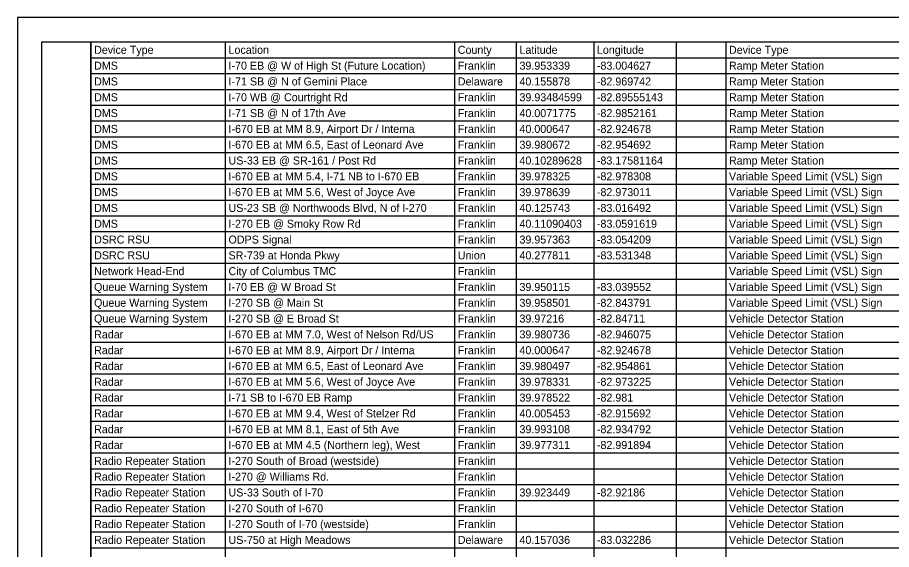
# Model space of a CAD drawing. Extents: x 0 to 34, y 0 to 22.
# Drawn here: x 0 to 17.86, y 11.13 to 22 of the extents above; entities that cross this region are included whole.
import ezdxf

# ---------------------------------------------------------------- set-up
doc = ezdxf.new("R2010")
doc.units = 0
for name, color, linetype in [('SH_Border', 7, 'Continuous'), ('SH_Cut_Line', 7, 'Continuous'), ('SH_Text', 7, 'Continuous')]:
    doc.layers.add(name, color=color, linetype=linetype)

msp = doc.modelspace()

# ---------------------------------------------------------------- linework, layer by layer
at = {"layer": 'SH_Border'}
for points in [[(0.5, 21.5), (1.5, 21.5), (1.5, 0.5), (0.5, 0.5)], [(1.5, 21.5), (33.5, 21.5), (33.5, 0.5), (1.5, 0.5)]]:
    msp.add_lwpolyline(points, close=True, dxfattribs=at)
at = {"layer": 'SH_Cut_Line'}
msp.add_lwpolyline([(0, 0), (34, 0), (34, 22), (0, 22)], close=True, dxfattribs=at)
at = {"layer": 'SH_Text'}
for p, q in [((1.5, 21.5), (27.214, 21.5)), ((1.5, 21.5), (1.5, 0.502)), ((4.246, 21.5), (4.246, 0.502)), ((8.93, 21.5), (8.93, 0.502)), ((10.19, 21.5), (10.19, 0.502)), ((11.773, 21.5), (11.773, 0.502)), ((13.453, 21.5), (13.453, 0.502)), ((14.47, 21.5), (14.47, 0.502)), ((1.5, 21.177), (27.214, 21.177)), ((1.5, 20.854), (27.214, 20.854)), ((1.5, 20.531), (27.214, 20.531)), ((1.5, 20.208), (27.214, 20.208)), ((1.5, 19.885), (27.214, 19.885)), ((1.5, 19.562), (27.214, 19.562)), ((1.5, 19.239), (27.214, 19.239)), ((1.5, 18.916), (27.214, 18.916)), ((1.5, 18.593), (27.214, 18.593)), ((1.5, 18.269), (27.214, 18.269)), ((1.5, 17.946), (27.214, 17.946)), ((1.5, 17.623), (27.214, 17.623)), ((1.5, 17.3), (27.214, 17.3)), ((1.5, 16.977), (27.214, 16.977)), ((1.5, 16.654), (27.214, 16.654)), ((1.5, 16.331), (27.214, 16.331)), ((1.5, 16.008), (27.214, 16.008)), ((1.5, 15.685), (27.214, 15.685)), ((1.5, 15.362), (27.214, 15.362)), ((1.5, 15.039), (27.214, 15.039)), ((1.5, 14.716), (27.214, 14.716)), ((1.5, 14.393), (27.214, 14.393)), ((1.5, 14.07), (27.214, 14.07)), ((1.5, 13.747), (27.214, 13.747)), ((1.5, 13.424), (27.214, 13.424)), ((1.5, 13.101), (27.214, 13.101)), ((1.5, 12.778), (27.214, 12.778)), ((1.5, 12.455), (27.214, 12.455)), ((1.5, 12.132), (27.214, 12.132)), ((1.5, 11.809), (27.214, 11.809)), ((1.5, 11.486), (27.214, 11.486)), ((1.5, 11.162), (27.214, 11.162))]:
    msp.add_line(p, q, dxfattribs=at)

# ---------------------------------------------------------------- texts
for s, height, p in [('Device Type', 0.16346, (1.565, 21.257)), ('Location', 0.1635, (4.311, 21.257)), ('Latitude', 0.1635, (10.255, 21.257)), ('Longitude', 0.1635, (11.837, 21.257)), ('Device Type', 0.16346, (14.535, 21.257)), ('County', 0.1635, (8.995, 21.257)), ('DMS', 0.1635, (1.565, 20.934)), ('I-70 EB @ W of High St (Future Location)', 0.16346, (4.311, 20.934)), ('Franklin', 0.1635, (8.995, 20.934)), ('39.953339', 0.1635, (10.255, 20.934)), ('-83.004627', 0.1635, (11.837, 20.934)), ('Ramp Meter Station', 0.16346, (14.535, 20.934)), ('DMS', 0.1635, (1.565, 20.611)), ('I-71 SB @ N of Gemini Place', 0.16346, (4.311, 20.611)), ('Delaware', 0.1635, (8.995, 20.611)), ('40.155878', 0.1635, (10.255, 20.611)), ('-82.969742', 0.1635, (11.837, 20.611)), ('Ramp Meter Station', 0.16346, (14.535, 20.611)), ('DMS', 0.1635, (1.565, 20.288)), ('I-70 WB @ Courtright Rd', 0.16346, (4.311, 20.288)), ('Franklin', 0.1635, (8.995, 20.288)), ('39.93484599', 0.16346, (10.255, 20.288)), ('-82.89555143', 0.16346, (11.837, 20.288)), ('Ramp Meter Station', 0.16346, (14.535, 20.288)), ('DMS', 0.1635, (1.565, 19.964)), ('I-71 SB @ N of 17th Ave', 0.16346, (4.311, 19.964)), ('Franklin', 0.1635, (8.995, 19.964)), ('40.0071775', 0.1635, (10.255, 19.964)), ('-82.9852161', 0.16346, (11.837, 19.964)), ('Ramp Meter Station', 0.16346, (14.535, 19.964)), ('DMS', 0.1635, (1.565, 19.641)), ('I-670 EB at MM 8.9, Airport Dr / Interna', 0.16346, (4.311, 19.641)), ('Franklin', 0.1635, (8.995, 19.641)), ('40.000647', 0.1635, (10.255, 19.641)), ('-82.924678', 0.1635, (11.837, 19.641)), ('Ramp Meter Station', 0.16346, (14.535, 19.641)), ('DMS', 0.1635, (1.565, 19.318)), ('I-670 EB at MM 6.5, East of Leonard Ave', 0.16346, (4.311, 19.318)), ('Franklin', 0.1635, (8.995, 19.318)), ('39.980672', 0.1635, (10.255, 19.318)), ('-82.954692', 0.1635, (11.837, 19.318)), ('Ramp Meter Station', 0.16346, (14.535, 19.318)), ('DMS', 0.1635, (1.565, 18.995)), ('US-33 EB @ SR-161 / Post Rd', 0.16346, (4.311, 18.995)), ('Franklin', 0.1635, (8.995, 18.995)), ('40.10289628', 0.16346, (10.255, 18.995)), ('-83.17581164', 0.16346, (11.837, 18.995)), ('Ramp Meter Station', 0.16346, (14.535, 18.995)), ('DMS', 0.1635, (1.565, 18.672)), ('I-670 EB at MM 5.4, I-71 NB to I-670 EB', 0.16346, (4.311, 18.672)), ('Franklin', 0.1635, (8.995, 18.672)), ('39.978325', 0.1635, (10.255, 18.672)), ('-82.978308', 0.1635, (11.837, 18.672)), ('Variable Speed Limit (VSL) Sign', 0.16346, (14.535, 18.672)), ('DMS', 0.1635, (1.565, 18.349)), ('I-670 EB at MM 5.6, West of Joyce Ave', 0.16346, (4.311, 18.349)), ('Franklin', 0.1635, (8.995, 18.349)), ('39.978639', 0.1635, (10.255, 18.349)), ('-82.973011', 0.1635, (11.837, 18.349)), ('Variable Speed Limit (VSL) Sign', 0.16346, (14.535, 18.349)), ('DMS', 0.1635, (1.565, 18.026)), ('US-23 SB @ Northwoods Blvd, N of I-270', 0.16346, (4.311, 18.026)), ('Franklin', 0.1635, (8.995, 18.026)), ('40.125743', 0.1635, (10.255, 18.026)), ('-83.016492', 0.1635, (11.837, 18.026)), ('Variable Speed Limit (VSL) Sign', 0.16346, (14.535, 18.026)), ('DMS', 0.1635, (1.565, 17.703)), ('I-270 EB @ Smoky Row Rd', 0.16346, (4.311, 17.703)), ('Franklin', 0.1635, (8.995, 17.703)), ('40.11090403', 0.16346, (10.255, 17.703)), ('-83.0591619', 0.16346, (11.837, 17.703)), ('Variable Speed Limit (VSL) Sign', 0.16346, (14.535, 17.703)), ('DSRC RSU', 0.1635, (1.565, 17.38)), ('ODPS Signal', 0.16346, (4.311, 17.38)), ('Franklin', 0.1635, (8.995, 17.38)), ('39.957363', 0.1635, (10.255, 17.38)), ('-83.054209', 0.1635, (11.837, 17.38)), ('Variable Speed Limit (VSL) Sign', 0.16346, (14.535, 17.38)), ('DSRC RSU', 0.1635, (1.565, 17.057)), ('SR-739 at Honda Pkwy', 0.16346, (4.311, 17.057)), ('Union', 0.1635, (8.995, 17.057)), ('40.277811', 0.1635, (10.255, 17.057)), ('-83.531348', 0.1635, (11.837, 17.057)), ('Variable Speed Limit (VSL) Sign', 0.16346, (14.535, 17.057)), ('Network Head-End', 0.16346, (1.565, 16.734)), ('City of Columbus TMC', 0.16346, (4.311, 16.734)), ('Franklin', 0.1635, (8.995, 16.734)), ('Variable Speed Limit (VSL) Sign', 0.16346, (14.535, 16.734)), ('Queue Warning System', 0.16346, (1.565, 16.411)), ('I-70 EB @ W Broad St', 0.16346, (4.311, 16.411)), ('Franklin', 0.1635, (8.995, 16.411)), ('39.950115', 0.1635, (10.255, 16.411)), ('-83.039552', 0.1635, (11.837, 16.411)), ('Variable Speed Limit (VSL) Sign', 0.16346, (14.535, 16.411)), ('Queue Warning System', 0.16346, (1.565, 16.088)), ('I-270 SB @ Main St', 0.16346, (4.311, 16.088)), ('Franklin', 0.1635, (8.995, 16.088)), ('39.958501', 0.1635, (10.255, 16.088)), ('-82.843791', 0.1635, (11.837, 16.088)), ('Variable Speed Limit (VSL) Sign', 0.16346, (14.535, 16.088)), ('Queue Warning System', 0.16346, (1.565, 15.765)), ('I-270 SB @ E Broad St', 0.16346, (4.311, 15.765)), ('Franklin', 0.1635, (8.995, 15.765)), ('39.97216', 0.1635, (10.255, 15.765)), ('-82.84711', 0.1635, (11.837, 15.765)), ('Vehicle Detector Station', 0.16346, (14.535, 15.765)), ('Radar', 0.1635, (1.565, 15.442)), ('I-670 EB at MM 7.0, West of Nelson Rd/US', 0.16346, (4.311, 15.442)), ('Franklin', 0.1635, (8.995, 15.442)), ('39.980736', 0.1635, (10.255, 15.442)), ('-82.946075', 0.1635, (11.837, 15.442)), ('Vehicle Detector Station', 0.16346, (14.535, 15.442)), ('Radar', 0.1635, (1.565, 15.119)), ('I-670 EB at MM 8.9, Airport Dr / Interna', 0.16346, (4.311, 15.119)), ('Franklin', 0.1635, (8.995, 15.119)), ('40.000647', 0.1635, (10.255, 15.119)), ('-82.924678', 0.1635, (11.837, 15.119)), ('Vehicle Detector Station', 0.16346, (14.535, 15.119)), ('Radar', 0.1635, (1.565, 14.796)), ('I-670 EB at MM 6.5, East of Leonard Ave', 0.16346, (4.311, 14.796)), ('Franklin', 0.1635, (8.995, 14.796)), ('39.980497', 0.1635, (10.255, 14.796)), ('-82.954861', 0.1635, (11.837, 14.796)), ('Vehicle Detector Station', 0.16346, (14.535, 14.796)), ('Radar', 0.1635, (1.565, 14.473)), ('I-670 EB at MM 5.6, West of Joyce Ave', 0.16346, (4.311, 14.473)), ('Franklin', 0.1635, (8.995, 14.473)), ('Vehicle Detector Station', 0.16346, (14.535, 14.473)), ('39.978331', 0.1635, (10.255, 14.473)), ('-82.973225', 0.1635, (11.837, 14.473)), ('Radar', 0.1635, (1.565, 14.15)), ('I-71 SB to I-670 EB Ramp', 0.16346, (4.311, 14.15)), ('Franklin', 0.1635, (8.995, 14.15)), ('39.978522', 0.1635, (10.255, 14.15)), ('-82.981', 0.1635, (11.837, 14.15)), ('Vehicle Detector Station', 0.16346, (14.535, 14.15)), ('Radar', 0.1635, (1.565, 13.827)), ('I-670 EB at MM 9.4, West of Stelzer Rd', 0.16346, (4.311, 13.827)), ('Franklin', 0.1635, (8.995, 13.827)), ('40.005453', 0.1635, (10.255, 13.827)), ('-82.915692', 0.1635, (11.837, 13.827)), ('Vehicle Detector Station', 0.16346, (14.535, 13.827)), ('Radar', 0.1635, (1.565, 13.504)), ('I-670 EB at MM 8.1, East of 5th Ave', 0.16346, (4.311, 13.504)), ('Franklin', 0.1635, (8.995, 13.504)), ('39.993108', 0.1635, (10.255, 13.504)), ('-82.934792', 0.1635, (11.837, 13.504)), ('Vehicle Detector Station', 0.16346, (14.535, 13.504)), ('Radar', 0.1635, (1.565, 13.181)), ('I-670 EB at MM 4.5 (Northern leg), West', 0.16346, (4.311, 13.181)), ('Franklin', 0.1635, (8.995, 13.181)), ('39.977311', 0.1635, (10.255, 13.181)), ('-82.991894', 0.1635, (11.837, 13.181)), ('Vehicle Detector Station', 0.16346, (14.535, 13.181)), ('Radio Repeater Station', 0.16346, (1.565, 12.857)), ('I-270 South of Broad (westside)', 0.16346, (4.311, 12.857)), ('Franklin', 0.1635, (8.995, 12.857)), ('Vehicle Detector Station', 0.16346, (14.535, 12.857)), ('Radio Repeater Station', 0.16346, (1.565, 12.534)), ('I-270 @ Williams Rd.', 0.16346, (4.311, 12.534)), ('Franklin', 0.1635, (8.995, 12.534)), ('Vehicle Detector Station', 0.16346, (14.535, 12.534)), ('Radio Repeater Station', 0.16346, (1.565, 12.211)), ('US-33 South of I-70', 0.16346, (4.311, 12.211)), ('Franklin', 0.1635, (8.995, 12.211)), ('39.923449', 0.1635, (10.255, 12.211)), ('-82.92186', 0.1635, (11.837, 12.211)), ('Vehicle Detector Station', 0.16346, (14.535, 12.211)), ('Radio Repeater Station', 0.16346, (1.565, 11.888)), ('I-270 South of I-670', 0.16346, (4.311, 11.888)), ('Franklin', 0.1635, (8.995, 11.888)), ('Vehicle Detector Station', 0.16346, (14.535, 11.888)), ('Radio Repeater Station', 0.16346, (1.565, 11.565)), ('I-270 South of I-70 (westside)', 0.16346, (4.311, 11.565)), ('Franklin', 0.1635, (8.995, 11.565)), ('Vehicle Detector Station', 0.16346, (14.535, 11.565)), ('Radio Repeater Station', 0.16346, (1.565, 11.242)), ('US-750 at High Meadows', 0.16346, (4.311, 11.242)), ('Delaware', 0.1635, (8.995, 11.242)), ('40.157036', 0.1635, (10.255, 11.242)), ('-83.032286', 0.1635, (11.837, 11.242)), ('Vehicle Detector Station', 0.16346, (14.535, 11.242))]:
    msp.add_text(s, height=height, dxfattribs=at).set_placement(p)

doc.saveas('drawing.dxf')
